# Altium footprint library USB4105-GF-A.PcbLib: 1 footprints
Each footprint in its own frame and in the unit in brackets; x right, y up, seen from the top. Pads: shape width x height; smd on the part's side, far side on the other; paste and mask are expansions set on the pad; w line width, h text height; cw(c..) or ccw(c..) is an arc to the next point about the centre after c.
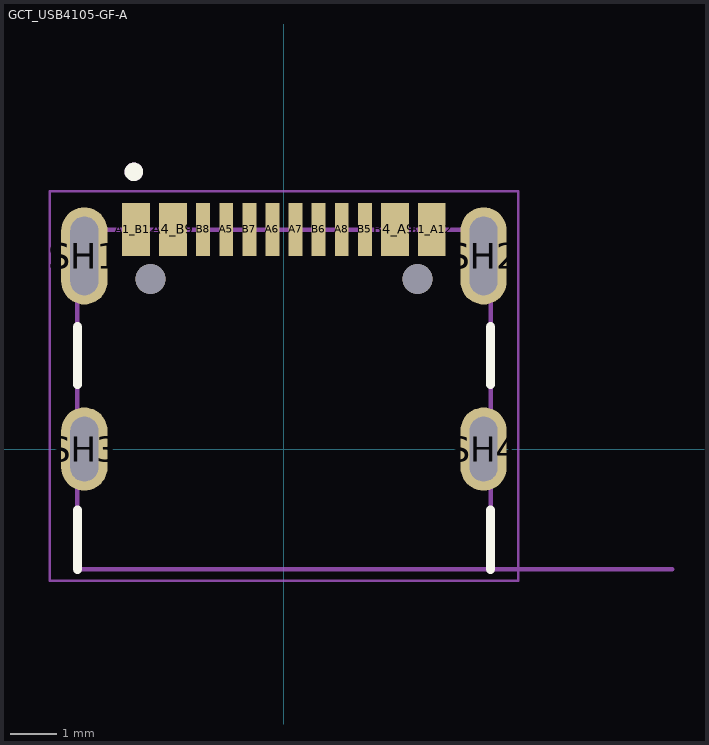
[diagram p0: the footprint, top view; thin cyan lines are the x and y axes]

## GCT_USB4105-GF-A [mm]
height 3.31
pads (18):
  rect 0.6x1.15 smd mask+0.05: A1_B12(-3.2,4.755) A4_B9(-2.4,4.755) B1_A12(3.2,4.755) B4_A9(2.4,4.755)
  rect 0.3x1.15 smd mask+0.05: A5(-1.25,4.755) A6(-0.25,4.755) A7(0.25,4.755) A8(1.25,4.755) B5(1.75,4.755) B6(0.75,4.755) B7(-0.75,4.755) B8(-1.75,4.755)
  oval 1x2.1 hole 0.6 slot 1.7 at 90 deg: SH1(-4.32,4.18) SH2(4.32,4.18)
  oval 1x1.8 hole 0.6 slot 1.4 at 90 deg: SH3(-4.32,0) SH4(4.32,0)
  round 0.65 hole 0.65 unplated: ""(-2.89,3.68) ""(2.89,3.68)
Top Overlay:
  circle w0.2: c-3.25,6 r0.1
  lines w0.2: -4.47,-2.6 -4.47,-1.32 ; -4.47,1.4 -4.47,2.65 ; 4.47,-2.6 4.47,-1.32 ; 4.47,1.4 4.47,2.65
Mechanical 13:
  circle w0.2: c-3.25,6 r0.1
  lines w0.1: 8.4,-2.6 4.47,-2.6 ; 4.47,-2.6 -4.47,-2.6 -4.47,4.75 4.47,4.75 4.47,-2.6
  text "PCB EDGE" at 5.4,-2.5 h0.41
Mechanical 15:
  lines w0.05: -5.07,-2.85 5.07,-2.85 5.07,5.58 -5.07,5.58 -5.07,-2.85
